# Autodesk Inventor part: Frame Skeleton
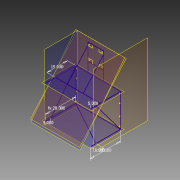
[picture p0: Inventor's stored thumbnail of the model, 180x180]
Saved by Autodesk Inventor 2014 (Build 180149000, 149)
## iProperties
Company: Autodesk, Inc.
Created: 2007-02
Part Number: Frame Skeleton
Document SubType Name: Modeling
Designer: Autodesk, Inc.
Density: 1 g/cm^3
Material: Generic
Appearance: Default
Author: Autodesk, Inc.
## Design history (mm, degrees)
sketch "Sketch1"
  geometry: L1 (-990.6, -304.8)-(-946.15, -304.8) reference; L2 (-990.6, -304.8)-(-990.6, 0) reference; L3 (-946.15, 469.9)-(-990.6, 469.9) reference; L4 (-990.6, 165.1)-(-990.6, 469.9) reference; L5 (19.05, -304.8)-(63.5, -304.8) reference; L6 (63.5, 0)-(63.5, -304.8) reference; L7 (63.5, 469.9)-(63.5, 165.1) reference; L8 (63.5, 469.9)-(19.05, 469.9) reference; L9 (-448.628, 1095.82)-(-448.628, 1025.97) reference; L10 (-334.328, 1025.97)-(-448.628, 1025.97) reference; L11 (-334.328, 1095.82)-(-334.328, 1025.97) reference; L12 (-334.328, 1095.82)-(-448.628, 1095.82) reference; L13 (-594.678, 1025.97)-(-594.678, 1095.82) reference; L14 (-594.678, 1095.82)-(-708.978, 1095.82) reference; L15 (-708.978, 1095.82)-(-708.978, 1025.97) reference; L16 (-594.678, 1025.97)-(-708.978, 1025.97) reference; L17 (-594.678, 702.12)-(-594.678, 771.97) reference; L18 (-594.678, 771.97)-(-708.978, 771.97) reference; L19 (-708.978, 771.97)-(-708.978, 702.12) reference; L20 (-594.678, 702.12)-(-708.978, 702.12) reference; L21 (-448.628, 771.97)-(-448.628, 702.12) reference; L22 (-334.328, 702.12)-(-448.628, 702.12) reference; L23 (-334.328, 771.97)-(-334.328, 702.12) reference; L24 (-334.328, 771.97)-(-448.628, 771.97) reference; L25 (-990.6, -304.8)-(-990.6, 469.9); L26 (63.5, -304.8)-(63.5, 469.9); L27 (63.5, -304.8)-(-990.6, -304.8); L28 (-990.6, 469.9)-(63.5, 469.9); L29 (-708.978, 1095.82)-(-334.328, 1095.82); L30 (-334.328, 702.12)-(-708.978, 702.12); L31 (-708.978, 1095.82)-(-708.978, 469.9); L32 (-334.328, 1095.82)-(-334.328, 469.9); C1 r 8.731 at (44.45, -254) reference; C2 r 8.731 at (44.45, -50.8) reference; C3 r 8.731 at (44.45, 215.9) reference; C4 r 8.731 at (44.45, 419.1) reference; C5 r 8.731 at (-971.55, 419.1) reference; C6 r 8.731 at (-971.55, 215.9) reference; C7 r 8.731 at (-971.55, -50.8) reference; C8 r 8.731 at (-971.55, -254) reference; C9 r 8.331 at (-369.253, 1057.72) reference; C10 r 8.331 at (-369.253, 1057.72) reference; C11 r 8.331 at (-674.053, 1057.72) reference; C12 r 8.331 at (-674.053, 740.22) reference; C13 r 8.331 at (-369.253, 740.22) reference
  constraints: 16 end point, 5 perpendicular, 2 collinear, 2 point on line, 1 parallel
  node "Reference1"
  node "Reference2"
  node "Reference3"
  node "Reference4"
  node "Reference5"
  node "Reference6"
  node "Reference7"
  node "Reference8"
  node "Reference9"
  node "Reference10"
  node "Reference11"
  node "Reference12"
  node "Reference13"
  node "Reference14"
  node "Reference15"
  node "Reference16"
  node "Reference17"
  node "Reference18"
  node "Reference19"
  node "Reference20"
  node "Reference21"
workplane "Work Plane2"
  workplane "Work Plane1"
sketch "Sketch2"
  geometry: L1 (304.8, 0)-(-469.9, 0) reference; L2 (304.8, 0)-(304.8, -711.2); L3 (-469.9, 0)-(-469.9, -711.2); L4 (304.8, 0)-(-469.9, -584.2)
  constraints: 6 end point, 2 parallel, 1 perpendicular, 1 point on line
  dimensions: "d1" = 711.2 distance of L1.start L2.end; "d5" = 127 distance of L3.end L4.end
workplane "Work Plane4"
  workplane "Work Plane3"
sketch "Sketch3"
  geometry: L1 (0, 0)-(774.7, 0) reference; L2 (0, 0)-(0, -711.2); L3 (774.7, 0)-(774.7, -711.2); L4 (774.7, 0)-(0, -584.2)
  constraints: 6 end point, 2 parallel, 1 perpendicular, 1 point on line
  dimensions: "d3" = 711.2 distance of L1.start L2.end (= d1); "d6" = 127 distance of L2.end L4.end
workplane "Work Plane5"
sketch "Sketch4"
  geometry: L1 (0, 1054.1)-(711.2, 1054.1) reference; L2 (0, 0)-(711.2, 0) reference; L3 (482.6, 1054.1)-(482.6, 0)
  constraints: 2 end point, 2 point on line, 1 perpendicular
  dimensions: "d4" = 482.6 distance from line of L1.start L3
workplane "Work Plane6"
sketch "Sketch5"
  geometry: L1 (-281.622, 790.366)-(772.478, 790.366) reference; L2 (0, 0)-(374.65, 0) reference
workplane "Work Plane7"
sketch "Sketch6"
  geometry: L1 (0, 0)-(711.2, 0) reference; L2 (0, 1054.1)-(584.2, 0)
  constraints: 2 end point, 1 point on line
  dimensions: "d7" = 127 distance of L1.end L2.end
workplane "Work Plane8"
sketch "Sketch7"
  geometry: L1 (656.272, 736.285)-(541.972, 736.285) reference; L2 (395.922, 736.285)-(281.622, 736.285) reference; L3 (0, 0)-(1054.1, 0) reference; L4 (656.272, 736.285)-(656.272, 0); L5 (281.622, 736.285)-(281.622, 0)
  constraints: 4 end point, 2 perpendicular, 2 point on line
other parameters: "d0" = 0, "d2" = 0
